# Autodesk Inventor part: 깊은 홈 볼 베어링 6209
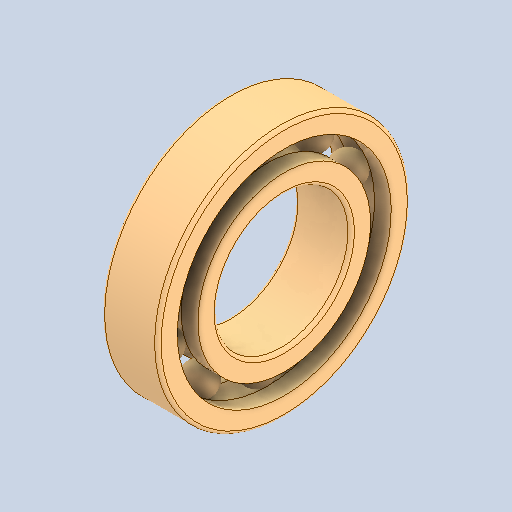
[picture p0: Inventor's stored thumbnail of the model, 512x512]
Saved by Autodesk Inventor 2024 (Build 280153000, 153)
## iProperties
Created: 2025-05
Part Number: 깊은 홈 볼 베어링 6209
Material: 강철, 연강
Description: 깊은 그루부 볼 베어링
Document SubType Name: Modeling
Designer: 11
Density: 7.85 g/cm^3
Appearance: 기본값
Author: jhkim
Sending System: Autodesk Inventor 2026
Preprocessor: ST-DEVELOPER v20.1
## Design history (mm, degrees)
node "깊은 홈 볼 베어링 62091"
node "솔리드1"
node "솔리드2"
node "솔리드3"
node "솔리드4"
node "솔리드5"
node "솔리드6"
node "솔리드7"
node "솔리드8"
node "솔리드9"
node "솔리드10"
node "솔리드11"
node "솔리드12"
body "Solid1"
node "Solid1:1"
node "Solid1:2"
node "Solid1:3"
node "Solid1:4"
node "Solid1:5"
node "Solid1:6"
node "Solid1:7"
node "Solid1:8"
node "Solid1:9"
node "Solid1:10"
node "Solid1:11"
